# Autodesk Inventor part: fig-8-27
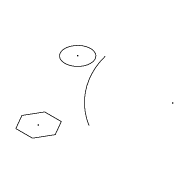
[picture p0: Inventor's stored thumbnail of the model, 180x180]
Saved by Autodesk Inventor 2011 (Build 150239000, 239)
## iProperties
Shininess: 77.0
Angle Display Precision: 2
Document Length Units: 11269
Document Angle Units: 11279
Document Time Units: 11290
Document Mass Units: 11283
Document Length Units Precision: 3
Document Angle Units Precision: 2
Created: 2001-12
Part Number: fig-8-27
Document SubType Name: Modeling
Designer: CADSoft
Density: 1 g/cm^3
Density: 0.0
Volumn: 0.0
Area: 0.0
PropertySet Name: Model Information
Control State: 0
Master: False
Checked Out: False
Author: CADSoft
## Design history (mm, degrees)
workplane "Work Plane3"
workplane "Work Plane4"
sketch "Sketch12"
  geometry: L1 (0, 10.598)-(9.178, -5.299); L2 (9.178, -5.299)-(-9.178, -5.299); L3 (-9.178, -5.299)-(0, 10.598); 1 further point
  constraints: 6 end point, 5 other
workplane "Work Plane5"
workplane "Work Plane6"
workplane "Work Plane7"
sketch "Sketch16"
  geometry: A1 r 72.799 centre (23.007, 110.594) between (0, 41.527) and (70, 54.995); 1 further point
  constraints: 2 point on circle, 1 centre point
body "Solid1"
sketch "Sketch1"
  geometry: L1 (19.387, 0)-(9.693, -16.79); L2 (9.693, -16.79)-(-9.693, -16.79); L3 (-9.693, -16.79)-(-19.387, 0); L4 (-19.387, 0)-(-9.693, 16.79); L5 (-9.693, 16.79)-(9.693, 16.79); L6 (9.693, 16.79)-(19.387, 0); 1 further point
  constraints: 12 end point, 11 other
sketch "Sketch2"
  geometry: C1 r 15 at (23.06, 22.535)
  constraints: 1 centre point
